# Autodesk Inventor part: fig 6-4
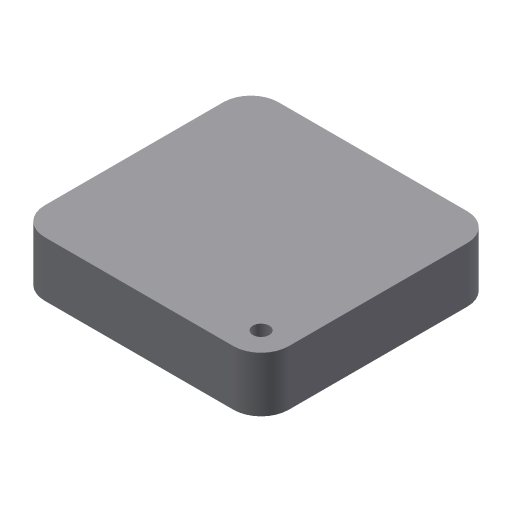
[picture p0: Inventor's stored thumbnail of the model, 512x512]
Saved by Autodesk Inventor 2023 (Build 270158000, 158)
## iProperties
Created: 2004-05
Part Number: fig 6-4
Document SubType Name: Modeling
Designer: CADCIM Technologies
Manufacturer: Standard
Standards Organization: Custom
Density: 1 g/cm^3
Material: Generic
Appearance: Default
Author: CADCIM Technologies
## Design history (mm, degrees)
sketch "Sketch1"
  geometry: L1 (0, 0)-(44.293, 0); L2 (44.293, 0)-(44.293, 42.442); L3 (44.293, 42.442)-(0, 42.442); L4 (0, 42.442)-(0, 0)
  constraints: 8 end point, 2 parallel, 1 horizontal, 1 perpendicular
extrude "Extrusion1" new body sketch "Sketch1" distance "d0" = 10; taper "d1" = 0 deg
fillet "Fillet1" dims "d2" = 5
sketch "Sketch2"
  geometry: 1 further point
sketch "Sketch3"
  geometry: L1 (5, 42.442)-(39.293, 42.442) reference; L2 (0, 5)-(0, 37.442) reference; L3 (39.293, 0)-(5, 0) reference; L4 (44.293, 37.442)-(44.293, 5) reference; A1 r 5 centre (39.293, 37.442) between (44.293, 37.442) and (39.293, 42.442) reference; A2 r 5 centre (5, 37.442) between (5, 42.442) and (0, 37.442) reference; A3 r 5 centre (5, 5) between (0, 5) and (5, 0) reference; A4 r 5 centre (39.293, 5) between (39.293, 0) and (44.293, 5) reference; 1 further point
hole "Hole2" diameter "d15" = 3; stored, may be unused: countersink angle "d19" = 90 deg, drill point angle "d21" = 118 deg; dims "d13" = 10, "d14" = 10, "d16" = 6, "d17" = 4, "d18" = 2, "d20" = 8
body "Solid1"
